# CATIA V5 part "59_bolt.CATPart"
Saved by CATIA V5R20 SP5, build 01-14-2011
Part number: 59_bolt
Bounding box of the stored display mesh (mm): x -11 to 11, y 129.409 to 151.315, z 94.35 to 115
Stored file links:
  C:\Documents and Settings\anizard\Bureau\13\59_bolt.CATPart
  C:\Documents and Settings\anizard\Bureau\13\anizard.CATProduct
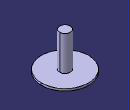
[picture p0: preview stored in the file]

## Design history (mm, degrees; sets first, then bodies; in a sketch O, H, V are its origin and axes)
Set1
  Plane1: linked copy from another document
  Point1: linked copy from another document
Body1 (main body)
  Sketch1 on Plane1, origin (0, 0, 99), H (1, 0, 0), V (0, 1, 0)
    circle A1 centre (0, 140.3619) radius 2.5
    point P1 (0, 140.3619)
    reference projected point E1 (0, 140.3619) from Point1
    radius A1 = 2.5
    coincidence: P1 E1
  Pad1: profile Sketch1, direction (0, 0, 1), length 16
  Sketch2 on start face of Pad1, origin (0, 0, 99), H (1, 0, 0), V (0, -1, 0)
    circle A1 centre (0, -140.3619) radius 11
    reference projected circle E1 centre (0, -140.3619) radius 2.5 from edge [start face of Pad1 | face of Pad1 from Sketch1.A1]
    radius A1 = 11
    concentricity: E1 A1
  Pad2: profile Sketch2, direction (0, 0, -1), length 1
  Sketch3 on end face of Pad2, origin (0, 0, 98), H (1, 0, 0), V (0, -1, 0)
    point P1 (0, -140.3619)
    point P2 (-2.3, -144.3457)
    point P3 (2.3, -144.3457)
    point P4 (4.6, -140.3619)
    point P5 (2.3, -136.3782)
    point P6 (-2.3, -136.3782)
    point P7 (-4.6, -140.3619)
    point P8 (0, -144.3457)
    line L1 (-2.3, -144.3457) -> (2.3, -144.3457)
    line L2 (2.3, -144.3457) -> (4.6, -140.3619)
    line L3 (4.6, -140.3619) -> (2.3, -136.3782)
    line L4 (2.3, -136.3782) -> (-2.3, -136.3782)
    line L5 (-2.3, -136.3782) -> (-4.6, -140.3619)
    line L6 (-4.6, -140.3619) -> (-2.3, -144.3457)
    construction line L7 (0, -140.3619) -> (0, -144.3457)
    construction circle A1 centre (0, -140.3619) radius 4.6
    construction arc A2 centre (-2.3, -136.3782) radius 4.6 from (2.3, -136.3782) to (-4.6, -140.3619) cw
    construction arc A3 centre (2.3, -144.3457) radius 4.6 from (4.6, -140.3619) to (-2.3, -144.3457) ccw
    reference projected circle E1 centre (0, -140.3619) radius 11 from edge [face of Pad2 from Sketch2.A1 | end face of Pad2]
    radius A1 = 4.6
    coincidence: A1 P2, A1 P3, A1 P4, A1 P5, A1 P6, A1 P7, A2 P1, A3 P1
    midpoint: P8 L1
    parallelism: L1 L4
    horizontal: L4 H
    concentricity: E1 A1
  Pad3: profile Sketch3, direction (0, 0, -1), length 3.65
